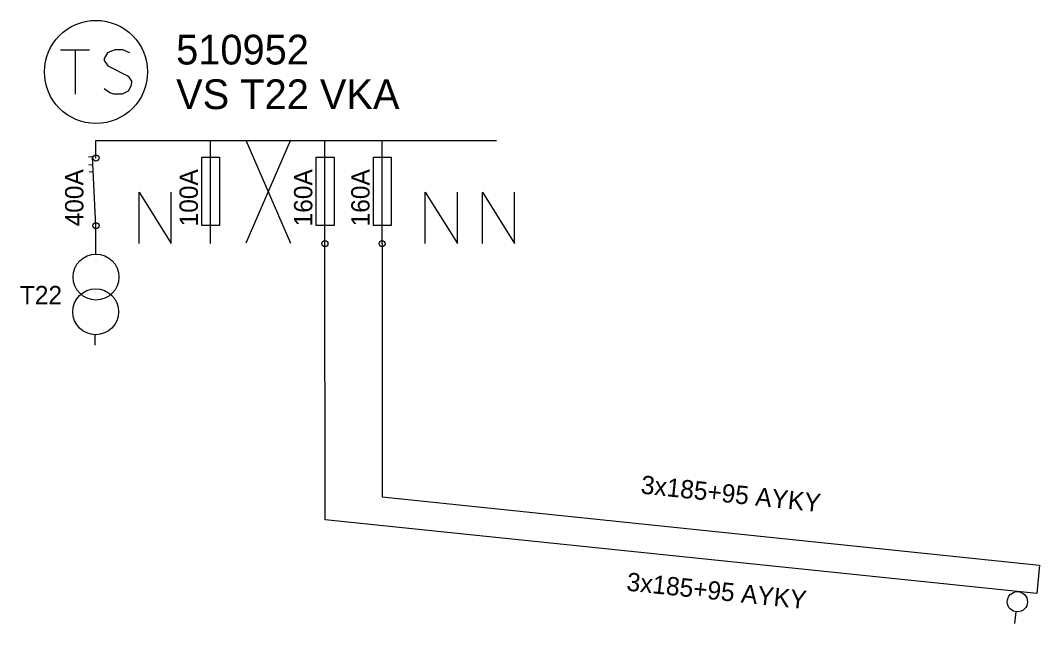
# Model space of a CAD drawing. Extents: x -536171 to -535465, y -1201641 to -1201274.
# Drawn here: x -536171.2 to -536082.1, y -1201327 to -1201274.2 of the extents above; entities that cross this region are included whole.
import ezdxf

# ---------------------------------------------------------------- set-up
doc = ezdxf.new("R2010")
doc.units = 0
for name, color, linetype in [('Default', 7, 'Continuous'), ('Vrstva 1', 7, 'Continuous'), ('Vrstva 2', 7, 'Continuous'), ('Vrstva 3', 7, 'Continuous')]:
    doc.layers.add(name, color=color, linetype=linetype)

# ---------------------------------------------------------------- blocks, each defined once
blk = doc.blocks.new('CONSUM')
at = {"layer": 'Default'}
blk.add_line((0, -2.797), (0, -1.767), dxfattribs=at)
blk.add_circle((0, -0.883), 0.883, dxfattribs=at)
blk = doc.blocks.new('STATIO4')
at = {"layer": 'Vrstva 1'}
for p, q in [((-3.106, 1.943), (-0.566, 1.943)), ((-1.821, 1.943), (-1.821, -1.943))]:
    blk.add_line(p, q, dxfattribs=at)
blk.add_lwpolyline([(2.953, 1.668), (2.341, 1.943), (1.637, 1.943), (0.995, 1.668), (0.719, 1.178), (0.719, 0.994), (1.025, 0.536), (2.8, -0.382), (3.106, -0.811), (3.076, -1.178), (2.8, -1.668), (2.28, -1.943), (1.546, -1.943), (1.209, -1.821), (0.719, -1.484)], dxfattribs=at)
blk.add_circle((0, 0), 4.505, dxfattribs=at)
blk = doc.blocks.new('TRAPLC')
at = {"layer": 'Vrstva 1'}
for p, q in [((0, -0.902), (0, 0)), ((-0.072, -8.87), (-0.072, -7.968))]:
    blk.add_line(p, q, dxfattribs=at)
for centre in [(0, -2.929), (-0.026, -5.964)]:
    blk.add_circle(centre, 2.005, dxfattribs=at)
blk = doc.blocks.new('TAPV18S1')
at = {"layer": 'Default'}
blk.add_lwpolyline([(-0.766, -1.438), (0.795, -1.438), (0.795, -7.414), (-0.766, -7.414)], close=True, dxfattribs=at)
at = {"layer": 'Vrstva 1'}
blk.add_line((0, -9.01), (0, 0), dxfattribs=at)
blk = doc.blocks.new('TAPVN1S1')
at = {"layer": 'Default'}
for p, q in [((0, -1.534), (0, 0)), ((-0.301, -1.427), (-0.653, -1.447)), ((0, -7.44), (-0.301, -1.427)), ((-0.267, -2.124), (-0.62, -2.144)), ((-0.242, -2.744), (-0.595, -2.764)), ((0, -9.01), (0, -7.44))]:
    blk.add_line(p, q, dxfattribs=at)
for centre in [(0, -1.534), (0, -7.44)]:
    blk.add_circle(centre, 0.265, dxfattribs=at)
blk = doc.blocks.new('TAPV18S2')
at = {"layer": 'Vrstva 1'}
for p, q in [((1.991, 0.048), (-1.896, -8.962)), ((-1.896, 0.048), (1.991, -8.962))]:
    blk.add_line(p, q, dxfattribs=at)
blk = doc.blocks.new('TAPV2')
at = {"layer": 'Default'}
blk.add_lwpolyline([(-1.231, -9.01), (-1.231, -4.505), (1.572, -9.01), (1.572, -4.505)], dxfattribs=at)
blk = doc.blocks.new('TAPV1')
at = {"layer": 'Vrstva 1'}
blk.add_circle((0, 0), 0.265, dxfattribs=at)

msp = doc.modelspace()

# ---------------------------------------------------------------- linework, layer by layer
at = {"layer": 'Vrstva 1'}
msp.add_lwpolyline([(-536139.569, -1201293.71), (-536139.573, -1201315.833), (-536082.128, -1201321.817), (-536082.386, -1201324.303), (-536144.553, -1201317.856), (-536144.569, -1201293.71)], dxfattribs=at)
at = {"layer": 'Vrstva 3'}
msp.add_lwpolyline([(-536164.569, -1201284.71), (-536129.569, -1201284.71)], dxfattribs=at)

# ---------------------------------------------------------------- block references
at = {"layer": 'Vrstva 2', "rotation": -6.277508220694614}
msp.add_blockref('CONSUM', (-536083.976, -1201324.139), dxfattribs=at)
at = {"layer": 'Vrstva 3'}
for name, p in [('STATIO4', (-536164.569, -1201278.71)), ('TAPV18S2', (-536149.569, -1201284.71)), ('TAPVN1S1', (-536164.569, -1201284.71)), ('TAPV18S1', (-536154.569, -1201284.71)), ('TAPV18S1', (-536144.569, -1201284.71)), ('TAPV18S1', (-536139.569, -1201284.71)), ('TAPV2', (-536159.569, -1201284.71)), ('TAPV2', (-536134.569, -1201284.71)), ('TAPV2', (-536129.569, -1201284.71)), ('TAPV1', (-536144.569, -1201293.71)), ('TAPV1', (-536139.569, -1201293.71)), ('TRAPLC', (-536164.569, -1201293.71))]:
    msp.add_blockref(name, p, dxfattribs=at)

# ---------------------------------------------------------------- texts
at = {"layer": 'Vrstva 1'}
for rotation, p in [(354.053, (-536117.02, -1201315.557)), (354.079, (-536118.264, -1201324.038))]:
    msp.add_text('3x185+95 AYKY', height=1.6, rotation=rotation, dxfattribs=at).set_placement(p)
at = {"layer": 'Vrstva 3'}
for s, height, p in [('510952', 2.6, (-536157.569, -1201278.06)), ('VS T22 VKA', 2.6, (-536157.569, -1201281.96)), ('T22', 1.6, (-536171.223, -1201299.01))]:
    msp.add_text(s, height=height, dxfattribs=at).set_placement(p)
for s, p in [('400A', (-536165.669, -1201292.21)), ('100A', (-536155.669, -1201292.21)), ('160A', (-536145.669, -1201292.21)), ('160A', (-536140.669, -1201292.21))]:
    msp.add_text(s, height=1.6, rotation=90, dxfattribs=at).set_placement(p)

doc.saveas('drawing.dxf')
